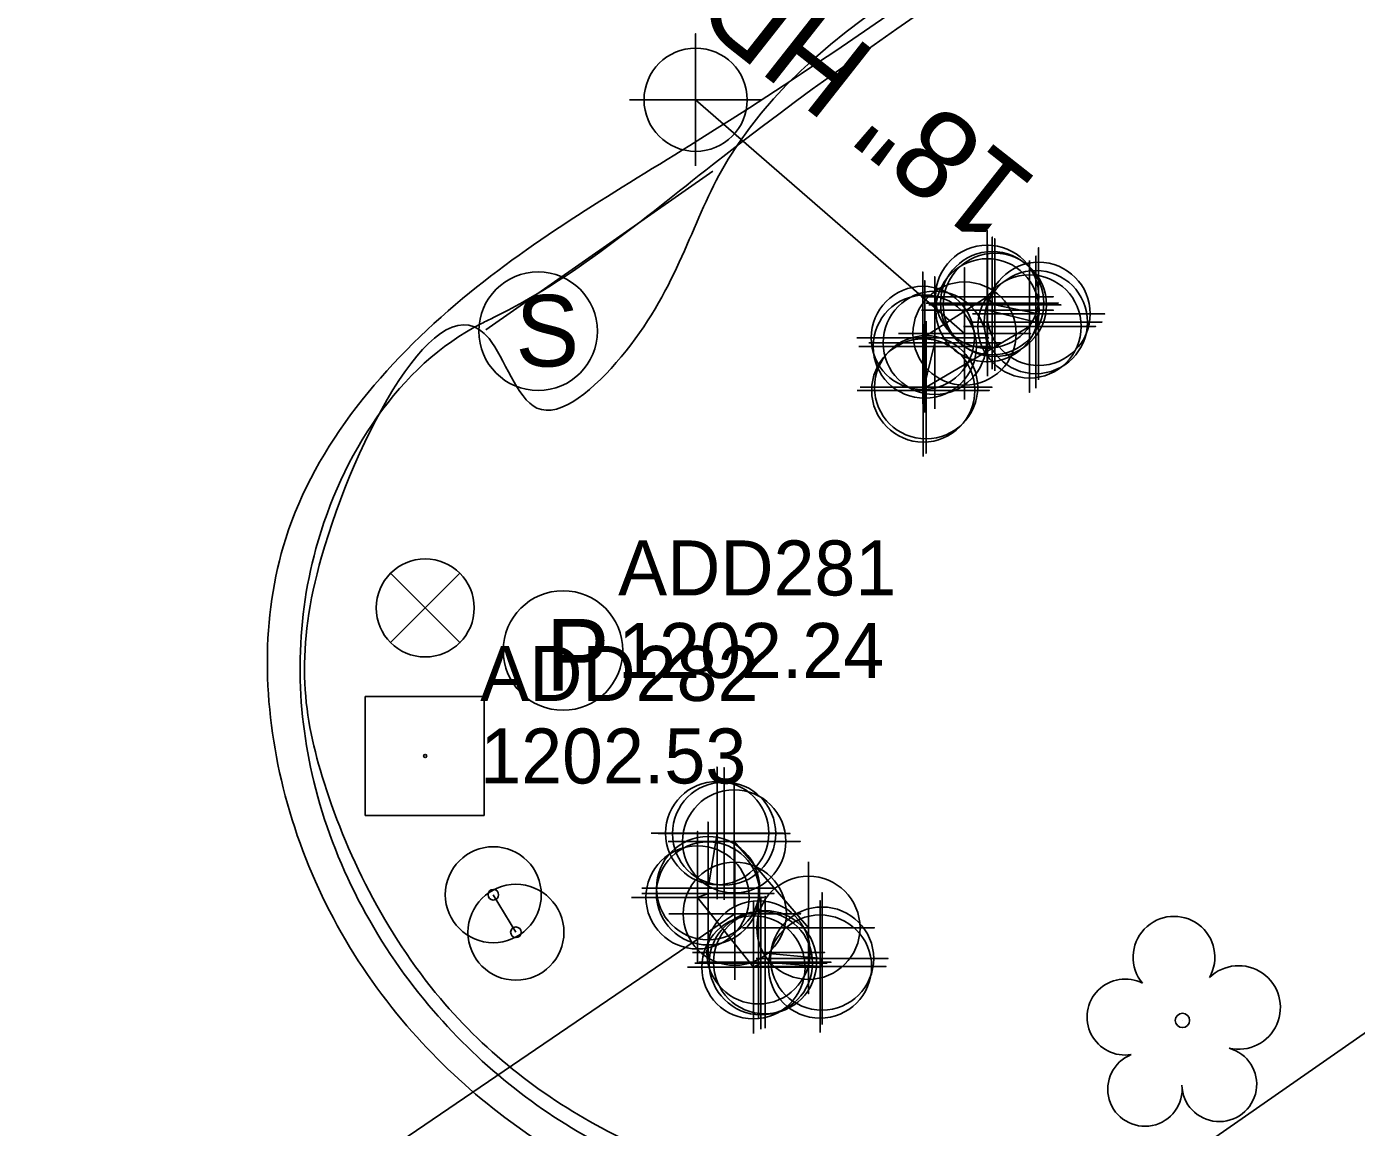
# Model space of a CAD drawing. Extents: x 1262092 to 1264624, y 774970 to 778314.
# Drawn here: x 1263560.4 to 1263620.8, y 776762.6 to 776812.6 of the extents above; entities that cross this region are included whole.
import ezdxf

# ---------------------------------------------------------------- set-up
doc = ezdxf.new("R2010")
doc.units = 0
for name, color, linetype in [('Cogo Default Point CELL', 7, 'Continuous'), ('Exist Horizontal Alignment Tick Small', 7, 'Continuous'), ('Exist Other Culture Area Outline Cogo Point CELL', 7, 'Continuous'), ('Exist Other Culture Sign Post CELL', 7, 'Continuous'), ('Exist Right of Way Line', 7, 'Continuous'), ('Exist Roads Curbs', 7, 'Continuous'), ('Exist Roads EOP', 7, 'Continuous'), ('Exist Structure Minor Head and End Wall', 7, 'Continuous'), ('Exist Structure Minor Head and End Wall Cogo Point CELL', 7, 'Continuous'), ('Exist Structure Minor Pipes HDPE 18 Inch', 7, 'Continuous'), ('Exist Structure Minor Pipes HDPE 18 Inch Cogo Point CELL', 7, 'Continuous'), ('Exist Structure Minor Pipes HDPE 18 Inch Text', 7, 'Continuous'), ('Exist Structure Minor Pipes HDPE 24 Inch', 7, 'Continuous'), ('Exist Structure Minor Pipes HDPE 24 Inch Cogo Point CELL', 7, 'Continuous'), ('Exist Structure Minor Storm Sewer Manhole CELL', 7, 'Continuous'), ('Exist Utilities Other Pole With Base Cogo Elevation', 7, 'Continuous'), ('Exist Utilities Other Pole With Base Cogo Number', 7, 'Continuous'), ('Exist Utilities Power Manhole CELL', 7, 'Continuous'), ('Exist Utilities Power Manhole Cogo Elevation', 7, 'Continuous'), ('Exist Utilities Power Manhole Cogo Number', 7, 'Continuous'), ('Exist Utilities Water Valve CELL', 7, 'Continuous'), ('Old_Level_4', 7, 'Continuous'), ('Prop Conc 2ft 9in Curb and Gutter', 7, 'Continuous'), ('Prop Superelevation Label', 7, 'Continuous')]:
    doc.layers.add(name, color=color, linetype=linetype)

msp = doc.modelspace()

# ---------------------------------------------------------------- linework, layer by layer
at = {"layer": 'Cogo Default Point CELL'}
for points in [[(1263590.815, 776812.312), (1263590.815, 776809.312)], [(1263590.815, 776812.312), (1263590.815, 776809.312)], [(1263587.815, 776809.312), (1263590.815, 776809.312)], [(1263587.815, 776809.312), (1263590.815, 776809.312)], [(1263590.815, 776809.312), (1263593.815, 776809.312)], [(1263590.815, 776809.312), (1263590.815, 776806.312)], [(1263590.815, 776809.312), (1263593.815, 776809.312)], [(1263590.815, 776809.312), (1263590.815, 776806.312)]]:
    msp.add_lwpolyline(points, dxfattribs=at)
msp.add_circle((1263590.815, 776809.312), 2.344, dxfattribs=at)
msp.add_circle((1263590.815, 776809.312), 2.344, dxfattribs=at)
at = {"layer": 'Exist Horizontal Alignment Tick Small'}
msp.add_line((1263612.928, 776767.476), (1263612.928, 776767.476), dxfattribs=at)
msp.add_circle((1263612.928, 776767.476), 0.326, dxfattribs=at)
for centre, radius, start, end in [((1263612.543, 776770.349), 1.856, 330.16508, 219.71335), ((1263615.477, 776768.064), 1.899, 257.1011, 134.19993), ((1263610.322, 776767.63), 1.727, 62.66361, 279.3457), ((1263611.224, 776764.355), 1.689, 111.56708, 6.23104), ((1263614.601, 776764.576), 1.698, 181.28216, 74.55999)]:
    msp.add_arc(centre, radius, start, end, dxfattribs=at)
at = {"layer": 'Exist Other Culture Area Outline Cogo Point CELL'}
for points in [[(1263605.982, 776802.011), (1263605.982, 776796.011), (1263605.982, 776799.011), (1263608.982, 776799.011), (1263602.982, 776799.011)], [(1263601.282, 776799.246), (1263601.282, 776793.246), (1263601.282, 776796.246), (1263604.282, 776796.246), (1263598.282, 776796.246)], [(1263592.565, 776778.611), (1263592.565, 776772.611), (1263592.565, 776775.611), (1263595.565, 776775.611), (1263589.565, 776775.611)], [(1263595.939, 776774.686), (1263595.939, 776768.686), (1263595.939, 776771.686), (1263598.939, 776771.686), (1263592.939, 776771.686)]]:
    msp.add_lwpolyline(points, dxfattribs=at)
for centre in [(1263605.982, 776799.011), (1263601.282, 776796.246), (1263592.565, 776775.611), (1263595.939, 776771.686)]:
    msp.add_circle(centre, 2.344, dxfattribs=at)
at = {"layer": 'Exist Other Culture Sign Post CELL'}
for centre, radius in [((1263581.625, 776773.188), 2.18), ((1263582.653, 776771.482), 2.18), ((1263581.625, 776773.188), 0.24), ((1263582.653, 776771.482), 0.24)]:
    msp.add_circle(centre, radius, dxfattribs=at)
at = {"layer": 'Exist Right of Way Line'}
msp.add_line((1263533.837, 776706.053), (1263681.329, 776808.775), dxfattribs=at)
at = {"layer": 'Exist Roads Curbs'}
msp.add_line((1263591.591, 776806.073), (1263581.281, 776798.858), dxfattribs=at)
for points in [[(1263764.818, 776873.267), (1263763.546, 776881.985), (1263753.652, 776893.476), (1263741.99, 776893.139), (1263725.162, 776887.942), (1263710.18, 776883.393), (1263690.356, 776874.854), (1263672.115, 776862.468), (1263640.916, 776840.698), (1263616.399, 776823.602), (1263591.577, 776806.354), (1263581.63, 776799.411), (1263581.094, 776799.148), (1263573.571, 776788.921), (1263573.474, 776778.335), (1263578.697, 776768.159), (1263586.559, 776761.82), (1263595.746, 776758.513)], [(1263764.225, 776873.537), (1263762.907, 776881.825), (1263753.487, 776892.876), (1263739.729, 776891.725), (1263725.232, 776887.245), (1263710.407, 776882.84), (1263690.448, 776874.324), (1263672.386, 776861.952), (1263641.161, 776840.152), (1263616.738, 776823.208), (1263591.872, 776805.875), (1263587.429, 776797.629), (1263583.607, 776795.304), (1263581.433, 776798.459), (1263573.826, 776788.547), (1263573.853, 776778.56), (1263579.221, 776768.471), (1263586.813, 776762.448), (1263595.846, 776759.023)]]:
    msp.add_spline(points, degree=3, dxfattribs=at)
at = {"layer": 'Exist Roads EOP'}
for points in [[(1263511.002, 776675.554), (1263536.409, 776690.705), (1263570.638, 776713.383), (1263606.789, 776738.887), (1263640.378, 776763.527), (1263671.487, 776785.825), (1263708.001, 776811.399), (1263736.423, 776831.656), (1263768.244, 776853.352), (1263805.247, 776879.669), (1263840.548, 776905.057), (1263875.279, 776930.442), (1263909.498, 776954.75), (1263950.366, 776982.405), (1263983.288, 777006.18), (1264027.541, 777035.52), (1264054.801, 777053.285), (1264082.168, 777072.955), (1264092.755, 777080.368)], [(1263764.915, 776866.164), (1263766.22, 776871.687), (1263764.785, 776882.341), (1263754.171, 776894.7), (1263741.714, 776894.48), (1263724.734, 776889.151), (1263709.907, 776884.795), (1263689.703, 776876.142), (1263671.266, 776863.443), (1263639.977, 776841.779), (1263615.582, 776824.671), (1263590.885, 776807.442), (1263580.232, 776800.279), (1263572.195, 776789.376), (1263572.083, 776778.044), (1263577.483, 776767.491), (1263585.834, 776760.717), (1263595.239, 776757.162), (1263606.827, 776754.703), (1263629.865, 776760.801)], [(1263532.952, 776644.883), (1263556.368, 776661.766), (1263588.744, 776685.135), (1263625.333, 776711.307), (1263659.49, 776736.267), (1263691.335, 776758.535), (1263726.37, 776783.82), (1263756.247, 776805.326), (1263773.741, 776816.649), (1263781.379, 776820.013)]]:
    msp.add_spline(points, degree=3, dxfattribs=at)
at = {"layer": 'Exist Structure Minor Head and End Wall'}
for points in [[(1263601.676, 776798.266), (1263601.155, 776796.102), (1263601.222, 776798.095), (1263601.131, 776798.49), (1263604.058, 776800.363), (1263604.285, 776800.07), (1263604.404, 776799.993), (1263606.396, 776799.584), (1263606.269, 776799.208), (1263604.068, 776799.745)], [(1263593.671, 776770.567), (1263596.558, 776770.286), (1263596.465, 776769.923), (1263593.968, 776770.12), (1263593.779, 776770.078), (1263593.439, 776769.889), (1263590.904, 776773.067), (1263591.377, 776773.249), (1263591.379, 776773.486), (1263591.793, 776775.989), (1263592.108, 776775.963)]]:
    msp.add_lwpolyline(points, dxfattribs=at)
at = {"layer": 'Exist Structure Minor Head and End Wall Cogo Point CELL'}
for points in [[(1263601.058, 776800.363), (1263607.058, 776800.363), (1263604.058, 776800.363), (1263604.058, 776803.363), (1263604.058, 776797.363)], [(1263601.068, 776799.745), (1263607.068, 776799.745), (1263604.068, 776799.745), (1263604.068, 776802.745), (1263604.068, 776796.745)], [(1263601.285, 776800.07), (1263607.285, 776800.07), (1263604.285, 776800.07), (1263604.285, 776803.07), (1263604.285, 776797.07)], [(1263601.404, 776799.993), (1263607.404, 776799.993), (1263604.404, 776799.993), (1263604.404, 776802.993), (1263604.404, 776796.993)], [(1263603.269, 776799.208), (1263609.269, 776799.208), (1263606.269, 776799.208), (1263606.269, 776802.208), (1263606.269, 776796.208)], [(1263603.396, 776799.584), (1263609.396, 776799.584), (1263606.396, 776799.584), (1263606.396, 776802.584), (1263606.396, 776796.584)], [(1263598.131, 776798.49), (1263604.131, 776798.49), (1263601.131, 776798.49), (1263601.131, 776801.49), (1263601.131, 776795.49)], [(1263598.222, 776798.095), (1263604.222, 776798.095), (1263601.222, 776798.095), (1263601.222, 776801.095), (1263601.222, 776795.095)], [(1263598.676, 776798.266), (1263604.676, 776798.266), (1263601.676, 776798.266), (1263601.676, 776801.266), (1263601.676, 776795.266)], [(1263598.155, 776796.102), (1263604.155, 776796.102), (1263601.155, 776796.102), (1263601.155, 776799.102), (1263601.155, 776793.102)], [(1263588.793, 776775.989), (1263594.793, 776775.989), (1263591.793, 776775.989), (1263591.793, 776778.989), (1263591.793, 776772.989)], [(1263589.108, 776775.963), (1263595.108, 776775.963), (1263592.108, 776775.963), (1263592.108, 776778.963), (1263592.108, 776772.963)], [(1263588.377, 776773.249), (1263594.377, 776773.249), (1263591.377, 776773.249), (1263591.377, 776776.249), (1263591.377, 776770.249)], [(1263588.379, 776773.486), (1263594.379, 776773.486), (1263591.379, 776773.486), (1263591.379, 776776.486), (1263591.379, 776770.486)], [(1263587.904, 776773.067), (1263593.904, 776773.067), (1263590.904, 776773.067), (1263590.904, 776776.067), (1263590.904, 776770.067)], [(1263590.671, 776770.567), (1263596.671, 776770.567), (1263593.671, 776770.567), (1263593.671, 776773.567), (1263593.671, 776767.567)], [(1263590.968, 776770.12), (1263596.968, 776770.12), (1263593.968, 776770.12), (1263593.968, 776773.12), (1263593.968, 776767.12)], [(1263593.558, 776770.286), (1263599.558, 776770.286), (1263596.558, 776770.286), (1263596.558, 776773.286), (1263596.558, 776767.286)], [(1263590.439, 776769.889), (1263596.439, 776769.889), (1263593.439, 776769.889), (1263593.439, 776772.889), (1263593.439, 776766.889)], [(1263590.779, 776770.078), (1263596.779, 776770.078), (1263593.779, 776770.078), (1263593.779, 776773.078), (1263593.779, 776767.078)], [(1263593.465, 776769.923), (1263599.465, 776769.923), (1263596.465, 776769.923), (1263596.465, 776772.923), (1263596.465, 776766.923)]]:
    msp.add_lwpolyline(points, dxfattribs=at)
for centre in [(1263604.058, 776800.363), (1263604.285, 776800.07), (1263604.404, 776799.993), (1263604.068, 776799.745), (1263606.269, 776799.208), (1263606.396, 776799.584), (1263601.131, 776798.49), (1263601.222, 776798.095), (1263601.676, 776798.266), (1263601.155, 776796.102), (1263591.793, 776775.989), (1263592.108, 776775.963), (1263591.377, 776773.249), (1263591.379, 776773.486), (1263590.904, 776773.067), (1263593.671, 776770.567), (1263596.558, 776770.286), (1263593.439, 776769.889), (1263593.779, 776770.078), (1263593.968, 776770.12), (1263596.465, 776769.923)]:
    msp.add_circle(centre, 2.344, dxfattribs=at)
at = {"layer": 'Exist Structure Minor Pipes HDPE 18 Inch'}
msp.add_line((1263603.031, 776798.688), (1263590.815, 776809.312), dxfattribs=at)
at = {"layer": 'Exist Structure Minor Pipes HDPE 18 Inch Cogo Point CELL'}
for points in [[(1263587.815, 776809.312), (1263593.815, 776809.312), (1263590.815, 776809.312), (1263590.815, 776812.312), (1263590.815, 776806.312)], [(1263600.031, 776798.688), (1263606.031, 776798.688), (1263603.031, 776798.688), (1263603.031, 776801.688), (1263603.031, 776795.688)]]:
    msp.add_lwpolyline(points, dxfattribs=at)
for centre in [(1263590.815, 776809.312), (1263603.031, 776798.688)]:
    msp.add_circle(centre, 2.344, dxfattribs=at)
at = {"layer": 'Exist Structure Minor Pipes HDPE 24 Inch'}
msp.add_line((1263592.591, 776772.324), (1263476.013, 776692.928), dxfattribs=at)
at = {"layer": 'Exist Structure Minor Pipes HDPE 24 Inch Cogo Point CELL'}
msp.add_lwpolyline([(1263589.591, 776772.324), (1263595.591, 776772.324), (1263592.591, 776772.324), (1263592.591, 776775.324), (1263592.591, 776769.324)], dxfattribs=at)
msp.add_circle((1263592.591, 776772.324), 2.344, dxfattribs=at)
at = {"layer": 'Exist Structure Minor Storm Sewer Manhole CELL'}
msp.add_circle((1263583.66, 776798.793), 2.694, dxfattribs=at)
at = {"layer": 'Exist Utilities Power Manhole CELL'}
msp.add_circle((1263584.794, 776784.287), 2.716, dxfattribs=at)
at = {"layer": 'Exist Utilities Water Valve CELL'}
msp.add_lwpolyline([(1263580.106, 776787.795), (1263576.956, 776784.645), (1263578.531, 776786.22), (1263580.106, 776784.645), (1263576.956, 776787.795)], dxfattribs=at)
msp.add_circle((1263578.531, 776786.22), 2.227, dxfattribs=at)
at = {"layer": 'Old_Level_4'}
msp.add_line((1263581.625, 776773.188), (1263582.653, 776771.482), dxfattribs=at)
at = {"layer": 'Prop Conc 2ft 9in Curb and Gutter'}
msp.add_line((1263578.53, 776779.493), (1263578.53, 776779.493), dxfattribs=at)
msp.add_lwpolyline([(1263575.805, 776782.193), (1263581.205, 776782.193), (1263581.205, 776776.793), (1263575.805, 776776.793), (1263575.805, 776782.193)], dxfattribs=at)
msp.add_circle((1263578.53, 776779.493), 0.0707, dxfattribs=at)
at = {"layer": 'Prop Superelevation Label'}
for p, q in [((1263605.982, 776799.011), (1263601.282, 776796.246)), ((1263592.565, 776775.611), (1263595.939, 776771.686))]:
    msp.add_line(p, q, dxfattribs=at)

# ---------------------------------------------------------------- texts
at = {"layer": 'Exist Structure Minor Pipes HDPE 18 Inch Text'}
msp.add_text('18" HDPE', height=4, rotation=141.78131, dxfattribs=at).set_placement((1263606.466, 776805.611))
at = {"layer": 'Exist Structure Minor Storm Sewer Manhole CELL'}
msp.add_text('S', height=3.25, dxfattribs=at).set_placement((1263582.629, 776797.193))
at = {"layer": 'Exist Utilities Other Pole With Base Cogo Elevation'}
msp.add_text('1202.53', height=2.5, dxfattribs=at).set_placement((1263581.03, 776778.243))
at = {"layer": 'Exist Utilities Other Pole With Base Cogo Number'}
msp.add_text('ADD282', height=2.5, dxfattribs=at).set_placement((1263581.03, 776781.993))
at = {"layer": 'Exist Utilities Power Manhole CELL'}
msp.add_text('P', height=3.25, dxfattribs=at).set_placement((1263584.007, 776782.465))
at = {"layer": 'Exist Utilities Power Manhole Cogo Elevation'}
msp.add_text('1202.24', height=2.5, dxfattribs=at).set_placement((1263587.294, 776783.037))
at = {"layer": 'Exist Utilities Power Manhole Cogo Number'}
msp.add_text('ADD281', height=2.5, dxfattribs=at).set_placement((1263587.294, 776786.787))

doc.saveas('drawing.dxf')
